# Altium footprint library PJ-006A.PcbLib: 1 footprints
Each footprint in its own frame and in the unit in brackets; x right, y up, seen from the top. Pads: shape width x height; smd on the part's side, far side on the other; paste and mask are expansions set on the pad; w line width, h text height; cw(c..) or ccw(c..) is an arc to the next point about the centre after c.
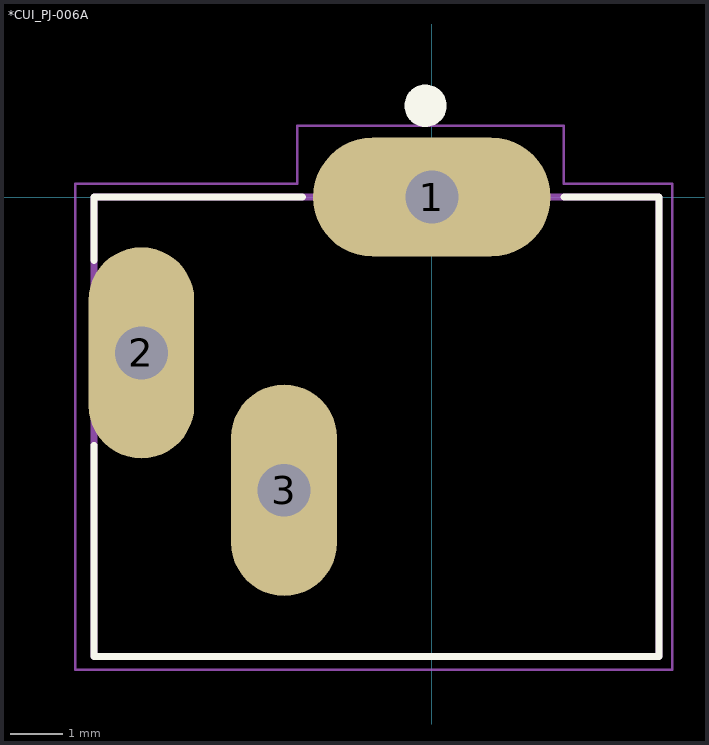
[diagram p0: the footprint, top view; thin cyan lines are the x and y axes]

## *CUI_PJ-006A [mm]
pads (3):
  oval 4.5x2.25 hole 1: 1(0,0)
  oval 2x4 hole 1: 2(-5.5,-2.95) 3(-2.8,-5.55)
Top Overlay:
  circle w0.4: c-0.12,1.73 r0.2
  lines w0.127: -6.4,-4.7 -6.4,-8.7 4.3,-8.7 4.3,0 2.5,0 ; -6.4,-1.2 -6.4,0 -2.45,0
Mechanical 1:
  lines w0: -6,-3.95 ccw(c-5.5,-3.95) -5.5,-4.45 ccw(c-5.5,-3.95) -5,-3.95 -5,-1.95 ccw(c-5.5,-1.95) -5.5,-1.45 ccw(c-5.5,-1.95) -6,-1.95 -6,-3.95 ; -3.3,-6.55 ccw(c-2.8,-6.55) -2.8,-7.05 ccw(c-2.8,-6.55) -2.3,-6.55 -2.3,-4.55 ccw(c-2.8,-4.55) -2.8,-4.05 ccw(c-2.8,-4.55) -3.3,-4.55 -3.3,-6.55 ; -1.75,0 cw(c-1.25,0) -1.25,0.5 1.25,0.5 cw(c1.25,0) 1.75,0 cw(c1.25,0) 1.25,-0.5 -1.25,-0.5 cw(c-1.25,0) -1.75,0
Mechanical 4:
  lines w0.127: -6.4,-8.7 -6.4,0 ; -6.4,-8.7 4.3,-8.7 ; -6.4,-8.7 -6.4,0 ; -6.4,-8.7 4.3,-8.7 ; -6.4,0 4.3,0 ; -6.4,0 4.3,0 ; 4.3,-8.7 4.3,0 ; 4.3,-8.7 4.3,0
Mechanical 16:
  lines w0.05: -6.75,-8.95 -6.75,0.25 -2.55,0.25 -2.55,1.35 2.5,1.35 2.5,0.25 4.55,0.25 4.55,-8.95 -6.75,-8.95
